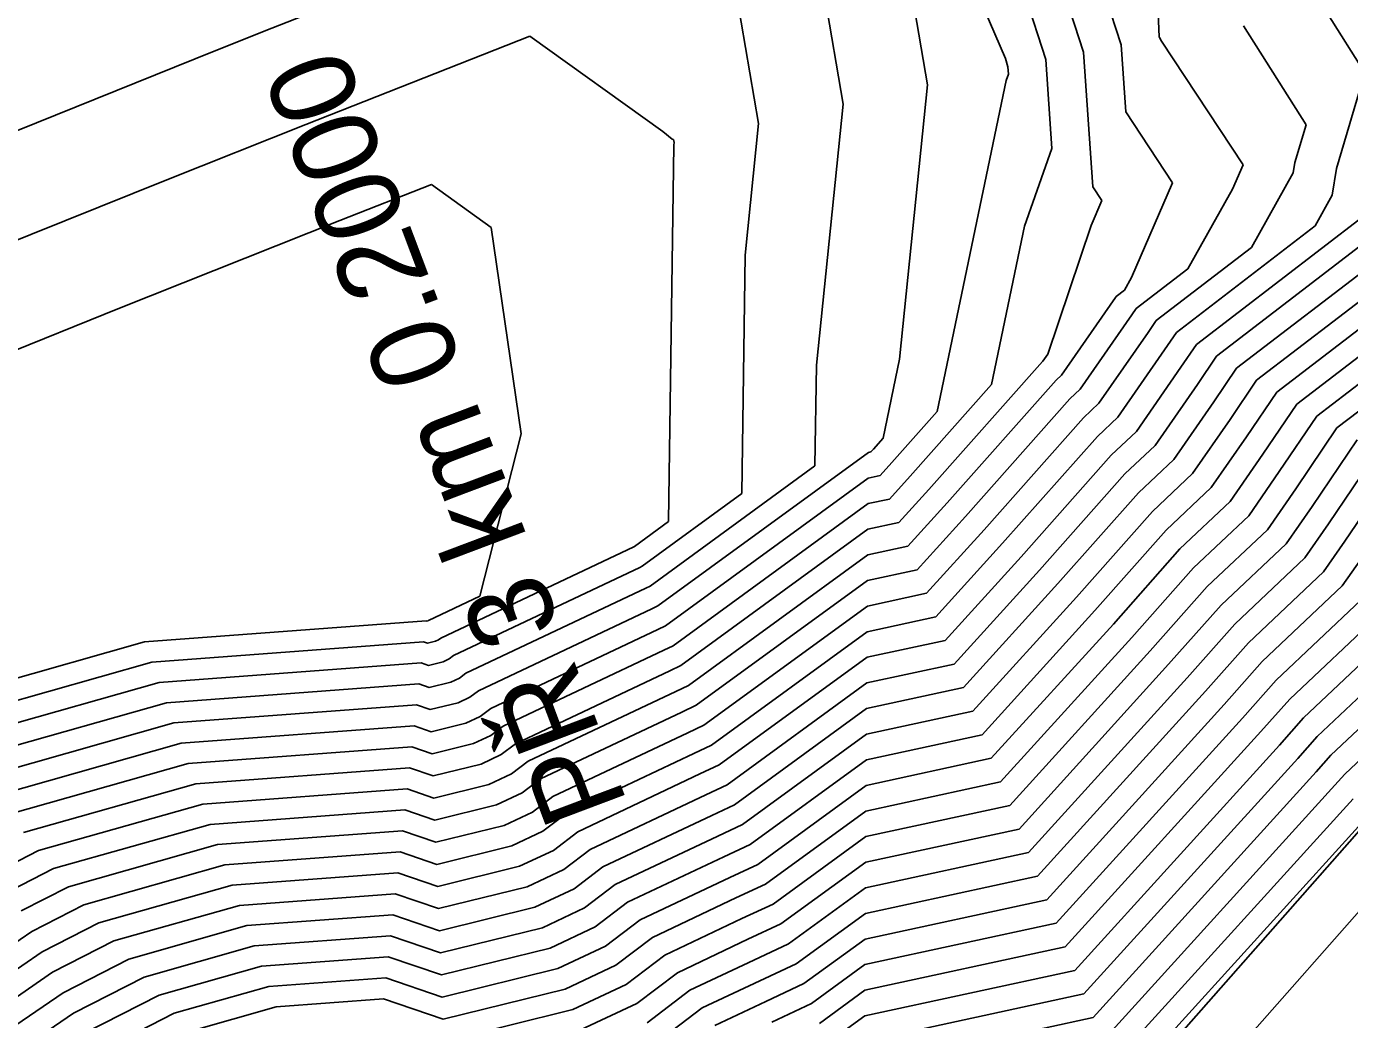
# Model space of a CAD drawing. Extents: x -549394 to -546608, y -1037055 to -1033629.
# Drawn here: x -547768.9 to -547627.3, y -1035754.3 to -1035648 of the extents above; entities that cross this region are included whole.
import ezdxf

# ---------------------------------------------------------------- set-up
doc = ezdxf.new("R2010")
doc.units = 0
for name, color, linetype in [('hlavni_vrst', 7, 'Continuous'), ('hrana_L', 7, 'Continuous'), ('norm_vrst', 7, 'Continuous'), ('x_popis_pricne_rezy_C11', 7, 'Continuous')]:
    doc.layers.add(name, color=color, linetype=linetype)

msp = doc.modelspace()

# ---------------------------------------------------------------- linework, layer by layer
at = {"layer": 'hlavni_vrst'}
for p, q in [((-547681.49, -1035656.31), (-547686.95, -1035624.25)), ((-547651.72, -1035649.98), (-547654.74, -1035640.65)), ((-547651.21, -1035657.15), (-547651.72, -1035649.98)), ((-547684.35, -1035684.25), (-547681.49, -1035656.31)), ((-547646.23, -1035664.72), (-547651.21, -1035657.15)), ((-547650.62, -1035674.87), (-547646.23, -1035664.72)), ((-547641.51, -1035683.3), (-547624.63, -1035670.35)), ((-547651.38, -1035676.22), (-547650.62, -1035674.87)), ((-547652.34, -1035677.01), (-547652.26, -1035676.9)), ((-547652.26, -1035676.9), (-547651.38, -1035676.22)), ((-547658.11, -1035685.31), (-547652.34, -1035677.01)), ((-547630.77, -1035689.69), (-547618.63, -1035680.39)), ((-547643.56, -1035686.32), (-547641.51, -1035683.3)), ((-547684.5, -1035695.02), (-547684.35, -1035684.25)), ((-547658.68, -1035685.86), (-547658.11, -1035685.31)), ((-547670.34, -1035698.99), (-547658.68, -1035685.86)), ((-547648.09, -1035692.84), (-547643.56, -1035686.32)), ((-547634.79, -1035695.63), (-547630.77, -1035689.69)), ((-547651.32, -1035695.89), (-547648.09, -1035692.84)), ((-547702.16, -1035707.89), (-547684.5, -1035695.02)), ((-547660.47, -1035706.19), (-547651.32, -1035695.89)), ((-547638.07, -1035700.36), (-547634.79, -1035695.63)), ((-547674.55, -1035703.62), (-547670.34, -1035698.99)), ((-547643.97, -1035705.93), (-547638.07, -1035700.36)), ((-547678.86, -1035704.55), (-547674.55, -1035703.62)), ((-547698.04, -1035718.53), (-547678.86, -1035704.55)), ((-547628.05, -1035707.88), (-547626.01, -1035704.94)), ((-547669.59, -1035716.23), (-547660.47, -1035706.19)), ((-547650.59, -1035713.39), (-547643.97, -1035705.93)), ((-547702.62, -1035708.1), (-547702.16, -1035707.89)), ((-547636.61, -1035715.96), (-547628.05, -1035707.88)), ((-547721.88, -1035717.22), (-547702.62, -1035708.1)), ((-547664.63, -1035728.84), (-547650.59, -1035713.39)), ((-547678.95, -1035718.25), (-547669.59, -1035716.23)), ((-547640.71, -1035720.58), (-547636.61, -1035715.96)), ((-547629.26, -1035726), (-547618.03, -1035715.4)), ((-547723.5, -1035718.18), (-547722.56, -1035717.74)), ((-547722.56, -1035717.74), (-547721.88, -1035717.22)), ((-547753.93, -1035720.37), (-547726.9, -1035718.36)), ((-547726.9, -1035718.36), (-547725.79, -1035718.74)), ((-547725.79, -1035718.74), (-547723.5, -1035718.18)), ((-547715.22, -1035726.64), (-547699.4, -1035719.16)), ((-547699.4, -1035719.16), (-547698.04, -1035718.53)), ((-547693.92, -1035729.16), (-547678.95, -1035718.25)), ((-547775.72, -1035726.53), (-547753.93, -1035720.37)), ((-547659.68, -1035741.45), (-547640.71, -1035720.58)), ((-547630.83, -1035727.78), (-547629.26, -1035726)), ((-547716.98, -1035727.98), (-547715.22, -1035726.64)), ((-547654.72, -1035754.06), (-547630.83, -1035727.78)), ((-547725.29, -1035730.58), (-547719.41, -1035729.12)), ((-547719.41, -1035729.12), (-547716.98, -1035727.98)), ((-547696.18, -1035730.22), (-547693.92, -1035729.16)), ((-547679.04, -1035731.96), (-547664.63, -1035728.84)), ((-547750.02, -1035731.22), (-547728.16, -1035729.59)), ((-547728.16, -1035729.59), (-547725.29, -1035730.58)), ((-547708.56, -1035736.07), (-547696.18, -1035730.22)), ((-547767.63, -1035736.2), (-547750.02, -1035731.22)), ((-547689.8, -1035739.8), (-547679.04, -1035731.96)), ((-547771.71, -1035738.28), (-547767.63, -1035736.2)), ((-547711.4, -1035738.23), (-547708.56, -1035736.07)), ((-547715.32, -1035740.07), (-547711.4, -1035738.23)), ((-547724.79, -1035742.41), (-547715.32, -1035740.07)), ((-547692.97, -1035741.27), (-547689.8, -1035739.8)), ((-547759.55, -1035745.87), (-547746.11, -1035742.06)), ((-547746.11, -1035742.06), (-547729.43, -1035740.83)), ((-547729.43, -1035740.83), (-547724.79, -1035742.41)), ((-547701.89, -1035745.5), (-547692.97, -1035741.27)), ((-547679.13, -1035745.66), (-547659.68, -1035741.45)), ((-547766.12, -1035749.22), (-547759.55, -1035745.87)), ((-547705.81, -1035748.47), (-547701.89, -1035745.5)), ((-547685.68, -1035750.43), (-547679.13, -1035745.66)), ((-547711.23, -1035751.02), (-547705.81, -1035748.47)), ((-547770.82, -1035752.44), (-547766.12, -1035749.22)), ((-547689.75, -1035752.33), (-547685.68, -1035750.43)), ((-547724.3, -1035754.25), (-547711.23, -1035751.02)), ((-547751.47, -1035755.54), (-547742.2, -1035752.91)), ((-547742.2, -1035752.91), (-547730.69, -1035752.06)), ((-547730.69, -1035752.06), (-547724.3, -1035754.25)), ((-547695.23, -1035754.92), (-547689.75, -1035752.33)), ((-547679.22, -1035759.36), (-547654.72, -1035754.06))]:
    msp.add_line(p, q, dxfattribs=at)
at = {"layer": 'hrana_L'}
for p, q in [((-547715.7, -1035835.54), (-547624.65, -1035732.28)), ((-547620.92, -1035736.65), (-547711.23, -1035838.83))]:
    msp.add_line(p, q, dxfattribs=at)
at = {"layer": 'norm_vrst'}
for p, q in [((-547664.12, -1035651.44), (-547674.42, -1035627.26)), ((-547647.66, -1035649.13), (-547648.44, -1035628.62)), ((-547655.76, -1035650.76), (-547661.83, -1035632)), ((-547672.44, -1035654.25), (-547675.2, -1035638.01)), ((-547659.8, -1035651.53), (-547663.22, -1035640.95)), ((-547690.54, -1035658.37), (-547693.3, -1035642.18)), ((-547729.59, -1035643.04), (-547742.66, -1035648.19)), ((-547625.63, -1035652.96), (-547629.59, -1035646.68)), ((-547742.66, -1035648.19), (-547748.84, -1035650.65)), ((-547631.93, -1035658.52), (-547638.61, -1035647.94)), ((-547715.03, -1035649.03), (-547739.01, -1035658.48)), ((-547700.8, -1035659.26), (-547715.03, -1035649.03)), ((-547647.63, -1035649.2), (-547647.66, -1035649.13)), ((-547647.4, -1035649.57), (-547647.63, -1035649.2)), ((-547638.67, -1035662.8), (-547647.4, -1035649.57)), ((-547748.84, -1035650.65), (-547792.11, -1035668.08)), ((-547663.84, -1035652.31), (-547664.12, -1035651.44)), ((-547654.74, -1035665.17), (-547655.76, -1035650.76)), ((-547663.78, -1035653.1), (-547663.84, -1035652.31)), ((-547659.13, -1035661.05), (-547659.8, -1035651.53)), ((-547675.44, -1035683.59), (-547672.44, -1035654.25)), ((-547671.41, -1035689.2), (-547664.02, -1035653.78)), ((-547664.02, -1035653.78), (-547663.78, -1035653.1)), ((-547628.66, -1035663.2), (-547625.63, -1035652.96)), ((-547739.01, -1035658.48), (-547753.9, -1035664.41)), ((-547691.98, -1035672.48), (-547690.54, -1035658.37)), ((-547633.13, -1035662.55), (-547631.93, -1035658.52)), ((-547699.8, -1035660.08), (-547700.8, -1035659.26)), ((-547700.17, -1035700.98), (-547699.62, -1035660.71)), ((-547699.64, -1035660.11), (-547699.8, -1035660.08)), ((-547699.59, -1035660.43), (-547699.64, -1035660.11)), ((-547699.62, -1035660.71), (-547699.59, -1035660.43)), ((-547662.07, -1035669.36), (-547659.13, -1035661.05)), ((-547633.31, -1035663.68), (-547633.13, -1035662.55)), ((-547639.81, -1035665.43), (-547638.67, -1035662.8)), ((-547637.76, -1035671.64), (-547633.31, -1035663.68)), ((-547629.12, -1035666.07), (-547628.66, -1035663.2)), ((-547753.9, -1035664.41), (-547781.99, -1035675.72)), ((-547725.57, -1035664.91), (-547735.36, -1035668.77)), ((-547719.18, -1035669.51), (-547725.57, -1035664.91)), ((-547653.78, -1035666.64), (-547654.74, -1035665.17)), ((-547644.57, -1035673.93), (-547639.81, -1035665.43)), ((-547654.92, -1035669.29), (-547653.78, -1035666.64)), ((-547630.96, -1035669.35), (-547629.12, -1035666.07)), ((-547643.66, -1035682.02), (-547625.83, -1035668.34)), ((-547735.36, -1035668.77), (-547758.96, -1035678.16)), ((-547715.97, -1035691.59), (-547719.18, -1035669.51)), ((-547665.61, -1035686.33), (-547662.07, -1035669.36)), ((-547659.59, -1035683.06), (-547654.92, -1035669.29)), ((-547645.81, -1035680.74), (-547630.96, -1035669.35)), ((-547692.33, -1035698), (-547691.98, -1035672.48)), ((-547647.96, -1035679.46), (-547637.76, -1035671.64)), ((-547639.37, -1035684.58), (-547623.43, -1035672.36)), ((-547650.11, -1035678.18), (-547644.57, -1035673.93)), ((-547637.22, -1035685.85), (-547622.23, -1035674.36)), ((-547635.07, -1035687.13), (-547621.03, -1035676.37)), ((-547758.96, -1035678.16), (-547771.86, -1035683.36)), ((-547650.58, -1035678.88), (-547650.11, -1035678.18)), ((-547656.1, -1035686.82), (-547650.58, -1035678.88)), ((-547648.83, -1035680.74), (-547647.96, -1035679.46)), ((-547632.92, -1035688.41), (-547619.83, -1035678.38)), ((-547654.1, -1035688.32), (-547648.83, -1035680.74)), ((-547647.07, -1035682.6), (-547645.81, -1035680.74)), ((-547652.09, -1035689.83), (-547647.07, -1035682.6)), ((-547645.32, -1035684.46), (-547643.66, -1035682.02)), ((-547628.62, -1035690.97), (-547617.44, -1035682.39)), ((-547677.21, -1035692.07), (-547675.44, -1035683.59)), ((-547672.32, -1035697.56), (-547660.15, -1035683.85)), ((-547660.15, -1035683.85), (-547660.11, -1035683.81)), ((-547660.11, -1035683.81), (-547659.59, -1035683.06)), ((-547650.09, -1035691.33), (-547645.32, -1035684.46)), ((-547641.81, -1035688.19), (-547639.37, -1035684.58)), ((-547674.3, -1035696.12), (-547665.61, -1035686.33)), ((-547657.21, -1035687.86), (-547656.1, -1035686.82)), ((-547640.05, -1035690.05), (-547637.22, -1035685.85)), ((-547668.37, -1035700.43), (-547657.21, -1035687.86)), ((-547646.08, -1035694.34), (-547641.81, -1035688.19)), ((-547638.3, -1035691.91), (-547635.07, -1035687.13)), ((-547676.27, -1035694.68), (-547671.41, -1035689.2)), ((-547655.74, -1035689.87), (-547654.1, -1035688.32)), ((-547636.54, -1035693.77), (-547632.92, -1035688.41)), ((-547666.39, -1035701.87), (-547655.74, -1035689.87)), ((-547654.27, -1035691.88), (-547652.09, -1035689.83)), ((-547644.08, -1035695.84), (-547640.05, -1035690.05)), ((-547633.03, -1035697.5), (-547628.62, -1035690.97)), ((-547720.38, -1035708.96), (-547715.97, -1035691.59)), ((-547678.25, -1035693.24), (-547677.21, -1035692.07)), ((-547664.42, -1035703.31), (-547654.27, -1035691.88)), ((-547652.8, -1035693.89), (-547650.09, -1035691.33)), ((-547642.08, -1035697.35), (-547638.3, -1035691.91)), ((-547631.27, -1035699.36), (-547626.47, -1035692.25)), ((-547701.34, -1035710.02), (-547678.78, -1035693.59)), ((-547678.78, -1035693.59), (-547678.51, -1035693.53)), ((-547678.51, -1035693.53), (-547678.25, -1035693.24)), ((-547662.44, -1035704.75), (-547652.8, -1035693.89)), ((-547640.07, -1035698.85), (-547636.54, -1035693.77)), ((-547629.52, -1035701.22), (-547624.32, -1035693.53)), ((-547677.52, -1035696.05), (-547676.27, -1035694.68)), ((-547649.85, -1035697.9), (-547646.08, -1035694.34)), ((-547627.76, -1035703.08), (-547622.17, -1035694.81)), ((-547700.52, -1035712.14), (-547678.8, -1035696.33)), ((-547678.8, -1035696.33), (-547677.52, -1035696.05)), ((-547676.53, -1035698.58), (-547674.3, -1035696.12)), ((-547648.38, -1035699.91), (-547644.08, -1035695.84)), ((-547702.99, -1035705.76), (-547692.33, -1035698)), ((-547675.54, -1035701.1), (-547672.32, -1035697.56)), ((-547658.49, -1035707.63), (-547649.85, -1035697.9)), ((-547646.91, -1035701.91), (-547642.08, -1035697.35)), ((-547636.07, -1035701.86), (-547633.03, -1035697.5)), ((-547699.69, -1035714.27), (-547678.82, -1035699.07)), ((-547678.82, -1035699.07), (-547676.53, -1035698.58)), ((-547645.44, -1035703.92), (-547640.07, -1035698.85)), ((-547634.06, -1035703.37), (-547631.27, -1035699.36)), ((-547703.81, -1035703.64), (-547700.17, -1035700.98)), ((-547673.56, -1035706.14), (-547668.37, -1035700.43)), ((-547656.52, -1035709.07), (-547648.38, -1035699.91)), ((-547698.87, -1035716.4), (-547678.84, -1035701.81)), ((-547678.84, -1035701.81), (-547675.54, -1035701.1)), ((-547672.56, -1035708.66), (-547666.39, -1035701.87)), ((-547654.54, -1035710.51), (-547646.91, -1035701.91)), ((-547642.5, -1035707.93), (-547636.07, -1035701.86)), ((-547632.06, -1035704.87), (-547629.52, -1035701.22)), ((-547724.54, -1035713.45), (-547703.91, -1035703.68)), ((-547703.91, -1035703.68), (-547703.81, -1035703.64)), ((-547671.57, -1035711.19), (-547664.42, -1035703.31)), ((-547641.03, -1035709.94), (-547634.06, -1035703.37)), ((-547630.05, -1035706.38), (-547627.76, -1035703.08)), ((-547670.58, -1035713.71), (-547662.44, -1035704.75)), ((-547652.56, -1035711.95), (-547645.44, -1035703.92)), ((-547639.55, -1035711.95), (-547632.06, -1035704.87)), ((-547723.21, -1035715.33), (-547703.26, -1035705.89)), ((-547703.26, -1035705.89), (-547702.99, -1035705.76)), ((-547678.88, -1035707.29), (-547673.56, -1035706.14)), ((-547638.08, -1035713.96), (-547630.05, -1035706.38)), ((-547697.22, -1035720.65), (-547678.88, -1035707.29)), ((-547668.6, -1035718.75), (-547658.49, -1035707.63)), ((-547648.61, -1035714.82), (-547642.5, -1035707.93)), ((-547725.87, -1035711.56), (-547720.38, -1035708.96)), ((-547678.89, -1035710.03), (-547672.56, -1035708.66)), ((-547667.61, -1035721.27), (-547656.52, -1035709.07)), ((-547635.14, -1035717.97), (-547626.05, -1035709.38)), ((-547720.54, -1035719.1), (-547701.98, -1035710.31)), ((-547701.98, -1035710.31), (-547701.34, -1035710.02)), ((-547696.39, -1035722.78), (-547678.89, -1035710.03)), ((-547666.62, -1035723.8), (-547654.54, -1035710.51)), ((-547646.64, -1035716.26), (-547641.03, -1035709.94)), ((-547633.67, -1035719.98), (-547624.04, -1035710.89)), ((-547756.28, -1035713.86), (-547726.14, -1035711.62)), ((-547726.14, -1035711.62), (-547726.08, -1035711.64)), ((-547726.08, -1035711.64), (-547725.96, -1035711.61)), ((-547725.96, -1035711.61), (-547725.91, -1035711.59)), ((-547725.91, -1035711.59), (-547725.87, -1035711.56)), ((-547701.33, -1035712.53), (-547700.52, -1035712.14)), ((-547678.91, -1035712.77), (-547671.57, -1035711.19)), ((-547665.63, -1035726.32), (-547652.56, -1035711.95)), ((-547644.66, -1035717.7), (-547639.55, -1035711.95)), ((-547725.14, -1035713.8), (-547724.79, -1035713.64)), ((-547724.79, -1035713.64), (-547724.54, -1035713.45)), ((-547719.21, -1035720.99), (-547701.33, -1035712.53)), ((-547695.57, -1035724.91), (-547678.91, -1035712.77)), ((-547678.93, -1035715.51), (-547670.58, -1035713.71)), ((-547632.2, -1035721.98), (-547622.04, -1035712.39)), ((-547780.56, -1035720.73), (-547756.28, -1035713.86)), ((-547755.5, -1035716.03), (-547726.4, -1035713.87)), ((-547726.4, -1035713.87), (-547725.98, -1035714.01)), ((-547725.98, -1035714.01), (-547725.14, -1035713.8)), ((-547717.88, -1035722.87), (-547700.69, -1035714.74)), ((-547700.69, -1035714.74), (-547699.69, -1035714.27)), ((-547663.64, -1035731.36), (-547648.61, -1035714.82)), ((-547642.69, -1035719.14), (-547638.08, -1035713.96)), ((-547630.73, -1035723.99), (-547620.04, -1035713.9)), ((-547778.95, -1035722.66), (-547755.5, -1035716.03)), ((-547754.72, -1035718.2), (-547726.65, -1035716.11)), ((-547726.65, -1035716.11), (-547725.88, -1035716.38)), ((-547725.88, -1035716.38), (-547724.32, -1035715.99)), ((-547724.32, -1035715.99), (-547723.68, -1035715.69)), ((-547723.68, -1035715.69), (-547723.21, -1035715.33)), ((-547700.05, -1035716.95), (-547698.87, -1035716.4)), ((-547694.75, -1035727.03), (-547678.93, -1035715.51)), ((-547662.65, -1035733.89), (-547646.64, -1035716.26)), ((-547716.55, -1035724.76), (-547700.05, -1035716.95)), ((-547661.66, -1035736.41), (-547644.66, -1035717.7)), ((-547638.74, -1035722.02), (-547635.14, -1035717.97)), ((-547627.78, -1035728.01), (-547616.03, -1035716.91)), ((-547777.33, -1035724.59), (-547754.72, -1035718.2)), ((-547721.44, -1035719.78), (-547720.54, -1035719.1)), ((-547678.97, -1035720.99), (-547668.6, -1035718.75)), ((-547660.67, -1035738.93), (-547642.69, -1035719.14)), ((-547753.15, -1035722.54), (-547727.15, -1035720.61)), ((-547727.15, -1035720.61), (-547725.69, -1035721.11)), ((-547725.69, -1035721.11), (-547722.69, -1035720.37)), ((-547722.69, -1035720.37), (-547721.44, -1035719.78)), ((-547698.76, -1035721.37), (-547697.22, -1035720.65)), ((-547636.76, -1035723.46), (-547633.67, -1035719.98)), ((-547721.87, -1035722.56), (-547720.33, -1035721.83)), ((-547720.33, -1035721.83), (-547719.21, -1035720.99)), ((-547713.88, -1035728.53), (-547698.76, -1035721.37)), ((-547693.1, -1035731.29), (-547678.97, -1035720.99)), ((-547678.98, -1035723.74), (-547667.61, -1035721.27)), ((-547658.69, -1035743.97), (-547638.74, -1035722.02)), ((-547634.78, -1035724.9), (-547632.2, -1035721.98)), ((-547774.1, -1035728.46), (-547753.15, -1035722.54)), ((-547752.37, -1035724.71), (-547727.41, -1035722.85)), ((-547727.41, -1035722.85), (-547725.59, -1035723.48)), ((-547725.59, -1035723.48), (-547721.87, -1035722.56)), ((-547719.21, -1035723.88), (-547717.88, -1035722.87)), ((-547712.55, -1035730.41), (-547698.12, -1035723.58)), ((-547698.12, -1035723.58), (-547696.39, -1035722.78)), ((-547657.7, -1035746.5), (-547636.76, -1035723.46)), ((-547772.48, -1035730.39), (-547752.37, -1035724.71)), ((-547725.49, -1035725.84), (-547721.05, -1035724.75)), ((-547721.05, -1035724.75), (-547719.21, -1035723.88)), ((-547718.09, -1035725.93), (-547716.55, -1035724.76)), ((-547697.47, -1035725.79), (-547695.57, -1035724.91)), ((-547692.27, -1035733.41), (-547678.98, -1035723.74)), ((-547679, -1035726.48), (-547666.62, -1035723.8)), ((-547656.7, -1035749.02), (-547634.78, -1035724.9)), ((-547632.81, -1035726.34), (-547630.73, -1035723.99)), ((-547751.59, -1035726.88), (-547727.66, -1035725.1)), ((-547727.66, -1035725.1), (-547725.49, -1035725.84)), ((-547720.23, -1035726.94), (-547718.09, -1035725.93)), ((-547711.22, -1035732.3), (-547697.47, -1035725.79)), ((-547691.45, -1035735.54), (-547679, -1035726.48)), ((-547679.02, -1035729.22), (-547665.63, -1035726.32)), ((-547655.71, -1035751.54), (-547632.81, -1035726.34)), ((-547770.87, -1035732.33), (-547751.59, -1035726.88)), ((-547750.8, -1035729.05), (-547727.91, -1035727.35)), ((-547727.91, -1035727.35), (-547725.39, -1035728.21)), ((-547725.39, -1035728.21), (-547720.23, -1035726.94)), ((-547696.83, -1035728), (-547694.75, -1035727.03)), ((-547769.25, -1035734.26), (-547750.8, -1035729.05)), ((-547715.86, -1035730.03), (-547713.88, -1035728.53)), ((-547709.89, -1035734.18), (-547696.83, -1035728)), ((-547690.63, -1035737.67), (-547679.02, -1035729.22)), ((-547653.73, -1035756.58), (-547628.86, -1035729.21)), ((-547628.86, -1035729.21), (-547627.78, -1035728.01)), ((-547718.59, -1035731.31), (-547715.86, -1035730.03)), ((-547714.74, -1035732.08), (-547712.55, -1035730.41)), ((-547652.74, -1035759.11), (-547626.88, -1035730.65)), ((-547749.24, -1035733.39), (-547728.42, -1035731.84)), ((-547728.42, -1035731.84), (-547725.19, -1035732.94)), ((-547725.19, -1035732.94), (-547718.59, -1035731.31)), ((-547717.77, -1035733.5), (-547714.74, -1035732.08)), ((-547695.54, -1035732.43), (-547693.1, -1035731.29)), ((-547679.06, -1035734.7), (-547663.64, -1035731.36)), ((-547651.75, -1035761.63), (-547624.91, -1035732.09)), ((-547766.02, -1035738.13), (-547749.24, -1035733.39)), ((-547725.09, -1035735.31), (-547717.77, -1035733.5)), ((-547713.63, -1035734.13), (-547711.22, -1035732.3)), ((-547707.22, -1035737.95), (-547695.54, -1035732.43)), ((-547694.9, -1035734.64), (-547692.27, -1035733.41)), ((-547748.46, -1035735.56), (-547728.67, -1035734.09)), ((-547728.67, -1035734.09), (-547725.09, -1035735.31)), ((-547716.96, -1035735.69), (-547713.63, -1035734.13)), ((-547712.51, -1035736.18), (-547709.89, -1035734.18)), ((-547705.89, -1035739.84), (-547694.9, -1035734.64)), ((-547688.98, -1035741.92), (-547679.06, -1035734.7)), ((-547679.07, -1035737.44), (-547662.65, -1035733.89)), ((-547764.4, -1035740.06), (-547748.46, -1035735.56)), ((-547747.68, -1035737.73), (-547728.92, -1035736.33)), ((-547728.92, -1035736.33), (-547724.99, -1035737.68)), ((-547724.99, -1035737.68), (-547716.96, -1035735.69)), ((-547716.14, -1035737.88), (-547712.51, -1035736.18)), ((-547694.25, -1035736.85), (-547691.45, -1035735.54)), ((-547679.09, -1035740.18), (-547661.66, -1035736.41)), ((-547762.79, -1035742), (-547747.68, -1035737.73)), ((-547704.56, -1035741.73), (-547694.25, -1035736.85)), ((-547693.61, -1035739.06), (-547690.63, -1035737.67)), ((-547688.15, -1035744.05), (-547679.07, -1035737.44)), ((-547770.59, -1035740.47), (-547766.02, -1035738.13)), ((-547746.89, -1035739.89), (-547729.17, -1035738.58)), ((-547729.17, -1035738.58), (-547724.89, -1035740.04)), ((-547724.89, -1035740.04), (-547716.14, -1035737.88)), ((-547710.28, -1035740.28), (-547707.22, -1035737.95)), ((-547703.23, -1035743.61), (-547693.61, -1035739.06)), ((-547679.11, -1035742.92), (-547660.67, -1035738.93)), ((-547769.47, -1035742.66), (-547764.4, -1035740.06)), ((-547761.17, -1035743.93), (-547746.89, -1035739.89)), ((-547714.5, -1035742.26), (-547710.28, -1035740.28)), ((-547709.16, -1035742.32), (-547705.89, -1035739.84)), ((-547687.33, -1035746.18), (-547679.09, -1035740.18)), ((-547768.35, -1035744.85), (-547762.79, -1035742)), ((-547708.05, -1035744.37), (-547704.56, -1035741.73)), ((-547692.32, -1035743.48), (-547688.98, -1035741.92)), ((-547745.33, -1035744.23), (-547729.68, -1035743.07)), ((-547729.68, -1035743.07), (-547724.69, -1035744.78)), ((-547724.69, -1035744.78), (-547714.5, -1035742.26)), ((-547713.68, -1035744.45), (-547709.16, -1035742.32)), ((-547700.56, -1035747.38), (-547692.32, -1035743.48)), ((-547686.51, -1035748.3), (-547679.11, -1035742.92)), ((-547772.35, -1035747.58), (-547768.35, -1035744.85)), ((-547767.23, -1035747.03), (-547761.17, -1035743.93)), ((-547757.94, -1035747.8), (-547745.33, -1035744.23)), ((-547724.6, -1035747.14), (-547713.68, -1035744.45)), ((-547712.86, -1035746.64), (-547708.05, -1035744.37)), ((-547706.93, -1035746.42), (-547703.23, -1035743.61)), ((-547691.68, -1035745.69), (-547688.15, -1035744.05)), ((-547679.15, -1035748.4), (-547658.69, -1035743.97)), ((-547744.55, -1035746.4), (-547729.93, -1035745.32)), ((-547729.93, -1035745.32), (-547724.6, -1035747.14)), ((-547699.23, -1035749.27), (-547691.68, -1035745.69)), ((-547691.04, -1035747.91), (-547687.33, -1035746.18)), ((-547771.58, -1035750.01), (-547767.23, -1035747.03)), ((-547756.32, -1035749.73), (-547744.55, -1035746.4)), ((-547743.76, -1035748.57), (-547730.19, -1035747.57)), ((-547730.19, -1035747.57), (-547724.5, -1035749.51)), ((-547724.5, -1035749.51), (-547712.86, -1035746.64)), ((-547712.04, -1035748.83), (-547706.93, -1035746.42)), ((-547704.7, -1035750.52), (-547700.56, -1035747.38)), ((-547679.17, -1035751.14), (-547657.7, -1035746.5)), ((-547765, -1035751.41), (-547757.94, -1035747.8)), ((-547754.7, -1035751.67), (-547743.76, -1035748.57)), ((-547724.4, -1035751.88), (-547712.04, -1035748.83)), ((-547697.9, -1035751.15), (-547691.04, -1035747.91)), ((-547690.39, -1035750.12), (-547686.51, -1035748.3)), ((-547684.86, -1035752.56), (-547679.15, -1035748.4)), ((-547679.18, -1035753.88), (-547656.7, -1035749.02)), ((-547763.88, -1035753.6), (-547756.32, -1035749.73)), ((-547742.98, -1035750.74), (-547730.44, -1035749.81)), ((-547730.44, -1035749.81), (-547724.4, -1035751.88)), ((-547710.41, -1035753.2), (-547704.7, -1035750.52)), ((-547703.58, -1035752.57), (-547699.23, -1035749.27)), ((-547696.57, -1035753.04), (-547690.39, -1035750.12)), ((-547770.06, -1035754.87), (-547765, -1035751.41)), ((-547762.76, -1035755.78), (-547754.7, -1035751.67)), ((-547753.09, -1035753.6), (-547742.98, -1035750.74)), ((-547702.46, -1035754.62), (-547697.9, -1035751.15)), ((-547684.03, -1035754.69), (-547679.17, -1035751.14)), ((-547679.2, -1035756.62), (-547655.71, -1035751.54)), ((-547724.2, -1035756.61), (-547710.41, -1035753.2)), ((-547709.59, -1035755.39), (-547703.58, -1035752.57)), ((-547701.35, -1035756.67), (-547696.57, -1035753.04)), ((-547689.11, -1035754.54), (-547684.86, -1035752.56)), ((-547769.29, -1035757.3), (-547763.88, -1035753.6)), ((-547761.64, -1035757.97), (-547753.09, -1035753.6)), ((-547683.21, -1035756.81), (-547679.18, -1035753.88))]:
    msp.add_line(p, q, dxfattribs=at)

# ---------------------------------------------------------------- texts
at = {"layer": 'x_popis_pricne_rezy_C11'}
msp.add_text('PŘ 3 km 0.2000', height=9.0627, rotation=110.6607, dxfattribs=at).set_placement((-547704.53, -1035731.17))

doc.saveas('drawing.dxf')
